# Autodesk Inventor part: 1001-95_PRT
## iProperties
Created: 2011-02
Part Number: 1001-95_PRT
Document SubType Name: Modeling
Designer: Administrator
Density: 1.06 g/cm^3
Material: ABS Plastic
Mass: 4.22144 g
Surface Area: 37.9131 cm^2
Volume: 3.98249 cm^3
Author: Administrator
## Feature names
1. Base1
